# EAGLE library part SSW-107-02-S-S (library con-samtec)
THROUGH-HOLE .025" SQ POST SOCKET Source: Samtec SSW.pdf
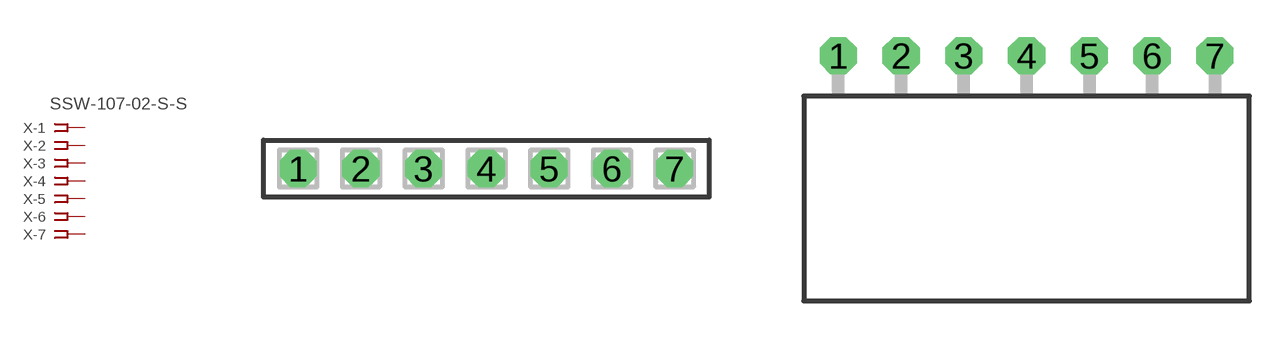
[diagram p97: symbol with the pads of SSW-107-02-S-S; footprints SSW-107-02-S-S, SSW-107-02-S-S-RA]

Designator prefix X; gates -1=FPINV -2=FPIN -3=FPIN -4=FPIN -5=FPIN -6=FPIN -7=FPIN

## SSW-107-02-S-S (MPN: SSW-107-02-S-S; OC_FARNELL: unknown; OC_NEWARK: 11P9433)  [SSW-107-02-S-S]
1  -1:1  pas
2  -2:1  pas
3  -3:1  pas
4  -4:1  pas
5  -5:1  pas
6  -6:1  pas
7  -7:1  pas

## SSW-107-02-S-S-RA (MPN: SSW-107-02-S-S-RA; OC_FARNELL: unknown; OC_NEWARK: 11P9434)  [SSW-107-02-S-S-RA]
Pads as for SSW-107-02-S-S

## Footprint SSW-107-02-S-S (pad centres in mm)
THROUGH-HOLE .025" SQ POST SOCKET Source: Samtec SSW.pdf
drill 1 pad 1.5 octagon: 1 -7.62,0; 2 -5.08,0; 3 -2.54,0; 4 0,0; 5 2.54,0; 6 5.08,0; 7 7.62,0

## Footprint SSW-107-02-S-S-RA (pad centres in mm)
THROUGH-HOLE .025" SQ POST SOCKET Source: Samtec SSW.pdf
drill 1 pad 1.5 octagon: 1 -7.62,1.524; 2 -5.08,1.524; 3 -2.54,1.524; 4 0,1.524; 5 2.54,1.524; 6 5.08,1.524; 7 7.62,1.524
